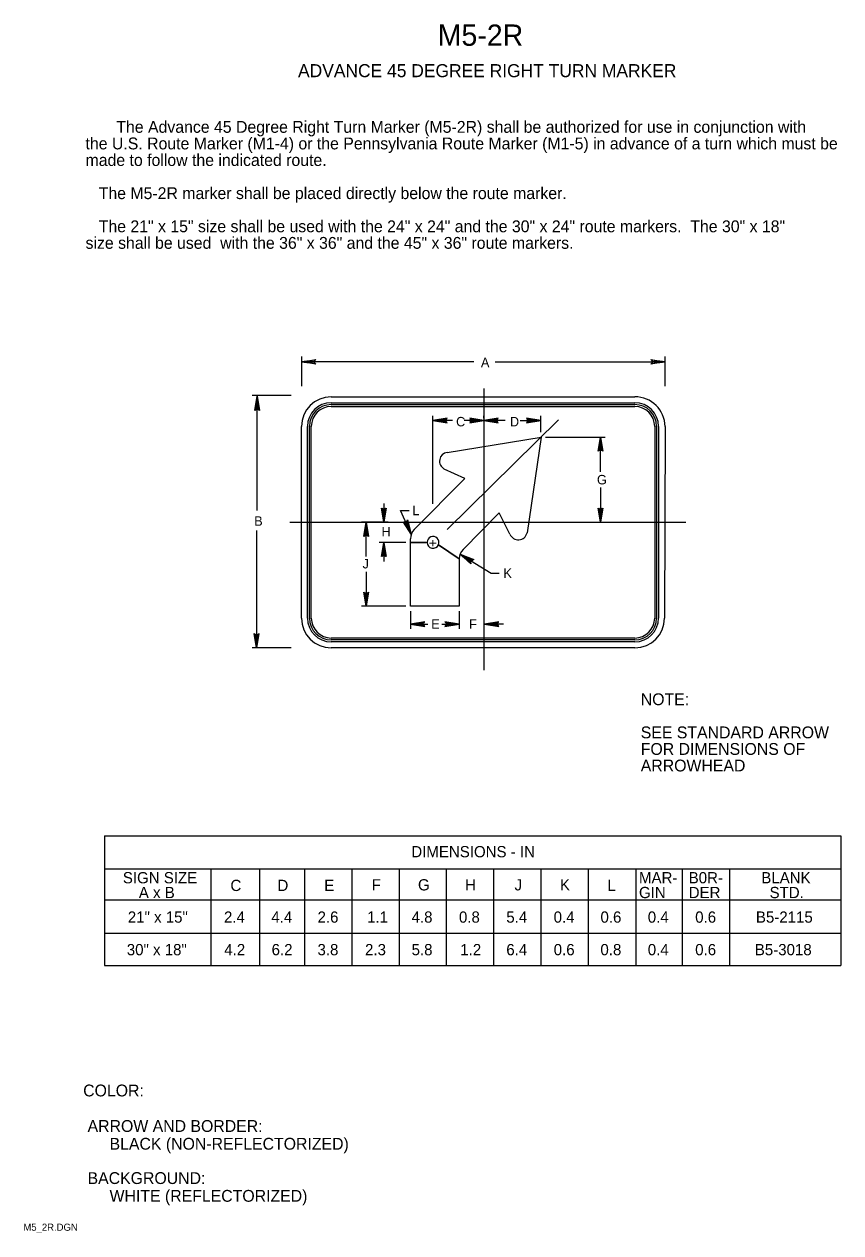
# Model space of a CAD drawing. Extents: x 0.013 to 0.185, y 0.004 to 0.259.
import ezdxf

# ---------------------------------------------------------------- set-up
doc = ezdxf.new("R2010")
doc.units = 0
for name, color, linetype in [('1', 7, 'Continuous'), ('2', 7, 'Continuous'), ('3', 7, 'Continuous')]:
    doc.layers.add(name, color=color, linetype=linetype)

msp = doc.modelspace()

# ---------------------------------------------------------------- linework, layer by layer
at = {"layer": '1'}
for p, q in [((0.185125, 0.08775000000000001), (0.185125, 0.060375)), ((0.16160297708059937, 0.08080009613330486), (0.16160297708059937, 0.06042509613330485))]:
    msp.add_line(p, q, dxfattribs=at)
at = {"layer": '2'}
for p, q in [((0.029625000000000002, 0.08775000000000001), (0.185125, 0.08775000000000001)), ((0.029625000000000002, 0.08775000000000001), (0.029625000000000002, 0.060375)), ((0.185125, 0.08075), (0.029625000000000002, 0.08075)), ((0.05210297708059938, 0.08080009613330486), (0.05210297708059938, 0.06042509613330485)), ((0.062375, 0.08075), (0.062375, 0.060375)), ((0.07187500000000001, 0.08075), (0.07187500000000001, 0.060375)), ((0.081875, 0.08075), (0.081875, 0.060375)), ((0.091875, 0.08075), (0.091875, 0.060375)), ((0.10175000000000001, 0.08075), (0.10175000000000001, 0.060375)), ((0.11175, 0.08075), (0.11175, 0.060375)), ((0.12175, 0.08075), (0.12175, 0.060375)), ((0.13175, 0.08075), (0.13175, 0.060375)), ((0.14185297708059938, 0.08080009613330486), (0.14185297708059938, 0.06042509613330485)), ((0.1516029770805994, 0.08080009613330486), (0.1516029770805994, 0.06042509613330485)), ((0.029625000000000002, 0.07425), (0.185125, 0.07425)), ((0.029625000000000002, 0.06725), (0.185125, 0.06725)), ((0.029625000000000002, 0.060375), (0.185125, 0.060375))]:
    msp.add_line(p, q, dxfattribs=at)
at = {"layer": '3'}
for p, q in [((0.07127993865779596, 0.1827356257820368), (0.07127993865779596, 0.18898593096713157)), ((0.148007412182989, 0.1827356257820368), (0.148007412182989, 0.18898593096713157)), ((0.07125000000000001, 0.18787500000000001), (0.07425, 0.18837500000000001)), ((0.074125, 0.18825), (0.07125000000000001, 0.18787500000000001)), ((0.07125000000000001, 0.18787500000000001), (0.074, 0.188)), ((0.074, 0.18775), (0.07125000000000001, 0.18787500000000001)), ((0.07125000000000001, 0.18787500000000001), (0.074125, 0.1875)), ((0.07425, 0.187375), (0.07125000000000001, 0.18787500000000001)), ((0.10761351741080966, 0.1878690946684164), (0.07126137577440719, 0.18786379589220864)), ((0.074, 0.188), (0.074125, 0.18825)), ((0.074125, 0.1875), (0.074, 0.18775)), ((0.07425, 0.18837500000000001), (0.074125, 0.18825)), ((0.074125, 0.1875), (0.07425, 0.187375)), ((0.11211351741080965, 0.1878690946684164), (0.14798851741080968, 0.18786379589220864)), ((0.145125, 0.18825), (0.145, 0.18837500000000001)), ((0.145, 0.18837500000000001), (0.148, 0.18787500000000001)), ((0.148, 0.18787500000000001), (0.145, 0.187375)), ((0.145, 0.187375), (0.145125, 0.1875)), ((0.145125, 0.18825), (0.14525, 0.188)), ((0.148, 0.18787500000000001), (0.145125, 0.18825)), ((0.145125, 0.1875), (0.148, 0.18787500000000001)), ((0.14525, 0.18775), (0.145125, 0.1875)), ((0.14525, 0.188), (0.148, 0.18787500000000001)), ((0.148, 0.18787500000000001), (0.14525, 0.18775)), ((0.10975, 0.18225), (0.10975, 0.12275)), ((0.06905786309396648, 0.18078209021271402), (0.060780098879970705, 0.18078209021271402)), ((0.061375, 0.177625), (0.061875, 0.180625)), ((0.061875, 0.180625), (0.0615, 0.17775)), ((0.06175, 0.177875), (0.061875, 0.180625)), ((0.06186351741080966, 0.15649756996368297), (0.06186351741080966, 0.18077012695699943)), ((0.061875, 0.180625), (0.062, 0.177875)), ((0.06225, 0.17775), (0.061875, 0.180625)), ((0.061875, 0.180625), (0.062375, 0.177625)), ((0.0775, 0.1805), (0.141625, 0.1805)), ((0.0775, 0.17925), (0.141625, 0.17925)), ((0.0775, 0.17885), (0.141625, 0.17885)), ((0.0615, 0.17775), (0.061375, 0.177625)), ((0.0615, 0.17775), (0.06175, 0.177875)), ((0.062, 0.177875), (0.06225, 0.17775)), ((0.062375, 0.177625), (0.06225, 0.17775)), ((0.0775, 0.17845), (0.141625, 0.17845)), ((0.099, 0.15787500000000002), (0.099, 0.1765)), ((0.10975, 0.176), (0.10975, 0.1765)), ((0.12175, 0.17300000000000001), (0.12175, 0.1765)), ((0.07125000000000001, 0.13375), (0.07125000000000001, 0.17425000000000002)), ((0.0725, 0.13375), (0.0725, 0.17425000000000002)), ((0.0729, 0.13375), (0.0729, 0.17425000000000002)), ((0.07330000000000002, 0.13375), (0.07330000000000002, 0.17425000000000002)), ((0.10200000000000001, 0.176), (0.099, 0.17550000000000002)), ((0.099, 0.17550000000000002), (0.10187500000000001, 0.175875)), ((0.10175000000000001, 0.175625), (0.099, 0.17550000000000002)), ((0.10312500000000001, 0.17550000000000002), (0.099, 0.17550000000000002)), ((0.099, 0.17550000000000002), (0.10175000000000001, 0.175375)), ((0.10187500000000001, 0.175125), (0.099, 0.17550000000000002)), ((0.099, 0.17550000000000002), (0.10200000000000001, 0.17500000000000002)), ((0.10187500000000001, 0.175875), (0.10175000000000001, 0.175625)), ((0.10175000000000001, 0.175375), (0.10187500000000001, 0.175125)), ((0.10187500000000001, 0.175875), (0.10200000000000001, 0.176)), ((0.10200000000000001, 0.17500000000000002), (0.10187500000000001, 0.175125)), ((0.1255, 0.175625), (0.10200000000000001, 0.1525)), ((0.10973851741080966, 0.1754947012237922), (0.10561351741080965, 0.1754947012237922)), ((0.10975, 0.17550000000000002), (0.10675, 0.176)), ((0.10675, 0.176), (0.106875, 0.175875)), ((0.10675, 0.17500000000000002), (0.10975, 0.17550000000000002)), ((0.106875, 0.175125), (0.10675, 0.17500000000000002)), ((0.107, 0.175625), (0.106875, 0.175875)), ((0.106875, 0.175875), (0.10975, 0.17550000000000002)), ((0.10975, 0.17550000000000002), (0.106875, 0.175125)), ((0.106875, 0.175125), (0.107, 0.175375)), ((0.10975, 0.17550000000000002), (0.107, 0.175625)), ((0.107, 0.175375), (0.10975, 0.17550000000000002)), ((0.11275, 0.176), (0.10975, 0.17550000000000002)), ((0.10975, 0.17550000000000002), (0.112625, 0.175875)), ((0.1125, 0.175625), (0.10975, 0.17550000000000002)), ((0.11375, 0.17550000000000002), (0.10975, 0.17550000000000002)), ((0.10975, 0.17550000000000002), (0.1125, 0.175375)), ((0.112625, 0.175125), (0.10975, 0.17550000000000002)), ((0.10975, 0.17550000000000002), (0.11275, 0.17500000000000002)), ((0.11423851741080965, 0.1754947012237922), (0.11023851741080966, 0.1754947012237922)), ((0.112625, 0.175875), (0.1125, 0.175625)), ((0.1125, 0.175375), (0.112625, 0.175125)), ((0.112625, 0.175875), (0.11275, 0.176)), ((0.11275, 0.17500000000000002), (0.112625, 0.175125)), ((0.11737500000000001, 0.17550000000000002), (0.12175, 0.17550000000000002)), ((0.12175, 0.17550000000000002), (0.11875000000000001, 0.176)), ((0.11875000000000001, 0.176), (0.11887500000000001, 0.175875)), ((0.11875000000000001, 0.17500000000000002), (0.12175, 0.17550000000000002)), ((0.11887500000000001, 0.175125), (0.11875000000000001, 0.17500000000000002)), ((0.11900000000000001, 0.175625), (0.11887500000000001, 0.175875)), ((0.11887500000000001, 0.175875), (0.12175, 0.17550000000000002)), ((0.12175, 0.17550000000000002), (0.11887500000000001, 0.175125)), ((0.11887500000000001, 0.175125), (0.11900000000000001, 0.175375)), ((0.12175, 0.17550000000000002), (0.11900000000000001, 0.175625)), ((0.11900000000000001, 0.175375), (0.12175, 0.17550000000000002)), ((0.14582499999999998, 0.17425000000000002), (0.14582499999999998, 0.13375)), ((0.146225, 0.17425000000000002), (0.146225, 0.13375)), ((0.146625, 0.17425000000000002), (0.146625, 0.13375)), ((0.148, 0.17425000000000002), (0.147875, 0.13375)), ((0.10200000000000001, 0.16875), (0.121875, 0.17200000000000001)), ((0.121875, 0.17200000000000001), (0.11887500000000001, 0.15175)), ((0.12275, 0.17200000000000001), (0.135375, 0.17200000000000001)), ((0.133875, 0.169), (0.134375, 0.17200000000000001)), ((0.134375, 0.17200000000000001), (0.134, 0.169125)), ((0.13425, 0.16925), (0.134375, 0.17200000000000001)), ((0.134375, 0.164625), (0.134375, 0.17200000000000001)), ((0.134375, 0.17200000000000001), (0.1345, 0.16925)), ((0.13475, 0.169125), (0.134375, 0.17200000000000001)), ((0.134375, 0.17200000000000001), (0.134875, 0.169)), ((0.134, 0.169125), (0.133875, 0.169)), ((0.134, 0.169125), (0.13425, 0.16925)), ((0.1345, 0.16925), (0.13475, 0.169125)), ((0.134875, 0.169), (0.13475, 0.169125)), ((0.10575, 0.16325), (0.101375, 0.16525)), ((0.095, 0.1525), (0.10575, 0.16325)), ((0.134375, 0.161375), (0.134375, 0.154)), ((0.088625, 0.154), (0.088125, 0.157)), ((0.088125, 0.157), (0.08825, 0.15687500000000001)), ((0.0885, 0.15675), (0.08825, 0.15687500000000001)), ((0.08825, 0.15687500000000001), (0.088625, 0.154)), ((0.088625, 0.154), (0.0885, 0.15675)), ((0.088625, 0.158), (0.088625, 0.154)), ((0.089125, 0.157), (0.088625, 0.154)), ((0.088625, 0.154), (0.089, 0.15687500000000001)), ((0.08875, 0.15675), (0.088625, 0.154)), ((0.089, 0.15687500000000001), (0.08875, 0.15675)), ((0.089, 0.15687500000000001), (0.089125, 0.157)), ((0.092125, 0.1565), (0.094, 0.1565)), ((0.094375, 0.1515), (0.092125, 0.1565)), ((0.113, 0.156), (0.105375, 0.14825)), ((0.11525, 0.1515), (0.113, 0.156)), ((0.134375, 0.154), (0.133875, 0.157)), ((0.133875, 0.157), (0.134, 0.15687500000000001)), ((0.13425, 0.15675), (0.134, 0.15687500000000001)), ((0.134, 0.15687500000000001), (0.134375, 0.154)), ((0.134375, 0.154), (0.13425, 0.15675)), ((0.134875, 0.157), (0.134375, 0.154)), ((0.134375, 0.154), (0.13475, 0.15687500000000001)), ((0.1345, 0.15675), (0.134375, 0.154)), ((0.13475, 0.15687500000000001), (0.1345, 0.15675)), ((0.13475, 0.15687500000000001), (0.134875, 0.157)), ((0.06875, 0.154), (0.152375, 0.154)), ((0.088875, 0.154), (0.083875, 0.154)), ((0.084375, 0.151), (0.084875, 0.154)), ((0.084875, 0.154), (0.0845, 0.151125)), ((0.08475, 0.15125), (0.084875, 0.154)), ((0.084875, 0.14675), (0.084875, 0.154)), ((0.084875, 0.154), (0.085, 0.15125)), ((0.08525, 0.151125), (0.084875, 0.154)), ((0.084875, 0.154), (0.085375, 0.151)), ((0.0895, 0.154), (0.08762500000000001, 0.154)), ((0.094375, 0.1515), (0.09275, 0.154)), ((0.09275, 0.154), (0.092875, 0.154)), ((0.093125, 0.154), (0.092875, 0.154)), ((0.092875, 0.154), (0.094375, 0.1515)), ((0.094375, 0.1515), (0.093125, 0.154)), ((0.0935, 0.15425), (0.093375, 0.154125)), ((0.093375, 0.154125), (0.094375, 0.1515)), ((0.0935, 0.15425), (0.093625, 0.1545)), ((0.094375, 0.1515), (0.0935, 0.15425)), ((0.093625, 0.1545), (0.094375, 0.1515)), ((0.133625, 0.154), (0.135375, 0.154)), ((0.06175, 0.15225421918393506), (0.06175, 0.1275)), ((0.0845, 0.151125), (0.084375, 0.151)), ((0.0845, 0.151125), (0.08475, 0.15125)), ((0.085, 0.15125), (0.08525, 0.151125)), ((0.085375, 0.151), (0.08525, 0.151125)), ((0.0932302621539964, 0.14975), (0.08762500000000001, 0.14975)), ((0.088125, 0.14675), (0.088625, 0.14975)), ((0.088625, 0.14975), (0.08825, 0.146875)), ((0.0885, 0.147), (0.088625, 0.14975)), ((0.088625, 0.14775), (0.088625, 0.14975)), ((0.088625, 0.14975), (0.08875, 0.147)), ((0.089, 0.146875), (0.088625, 0.14975)), ((0.088625, 0.14975), (0.089125, 0.14675)), ((0.09425, 0.14975), (0.09425, 0.1505)), ((0.09775, 0.14975), (0.09425, 0.14975)), ((0.09425, 0.14975), (0.09775, 0.14975)), ((0.09425, 0.13625), (0.09425, 0.14975)), ((0.1045, 0.14625), (0.1001544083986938, 0.14927058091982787)), ((0.1001544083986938, 0.14927058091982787), (0.1045, 0.14625)), ((0.08825, 0.146875), (0.088125, 0.14675)), ((0.08825, 0.146875), (0.0885, 0.147)), ((0.088625, 0.14775), (0.088625, 0.14575)), ((0.08875, 0.147), (0.089, 0.146875)), ((0.089125, 0.14675), (0.089, 0.146875)), ((0.1045, 0.14625), (0.1045, 0.13625)), ((0.10475, 0.14725), (0.11125, 0.14325000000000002)), ((0.107, 0.145625), (0.10475, 0.14725)), ((0.10475, 0.14725), (0.107, 0.145375)), ((0.107, 0.14525), (0.10475, 0.14725)), ((0.10475, 0.14725), (0.107125, 0.145875)), ((0.107375, 0.146), (0.10475, 0.14725)), ((0.10475, 0.14725), (0.107625, 0.146125)), ((0.107, 0.145375), (0.107, 0.145625)), ((0.107125, 0.145875), (0.107375, 0.146)), ((0.107625, 0.146125), (0.107375, 0.146)), ((0.084875, 0.14350000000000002), (0.084875, 0.13625)), ((0.107, 0.145375), (0.107, 0.14525)), ((0.11125, 0.14325000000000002), (0.113, 0.14325000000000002)), ((0.084875, 0.13625), (0.084375, 0.13925)), ((0.084375, 0.13925), (0.0845, 0.139125)), ((0.08475, 0.139), (0.0845, 0.139125)), ((0.0845, 0.139125), (0.084875, 0.13625)), ((0.084875, 0.13625), (0.08475, 0.139)), ((0.085375, 0.13925), (0.084875, 0.13625)), ((0.084875, 0.13625), (0.08525, 0.139125)), ((0.085, 0.139), (0.084875, 0.13625)), ((0.08525, 0.139125), (0.085, 0.139)), ((0.08525, 0.139125), (0.085375, 0.13925)), ((0.09325, 0.13625), (0.083875, 0.13625)), ((0.1045, 0.13625), (0.09425, 0.13625)), ((0.09425, 0.13525), (0.09425, 0.1315)), ((0.09725, 0.133), (0.09425, 0.1325)), ((0.09425, 0.1325), (0.097125, 0.132875)), ((0.097125, 0.132875), (0.097, 0.132625)), ((0.097125, 0.132875), (0.09725, 0.133)), ((0.1045, 0.1325), (0.1015, 0.133)), ((0.1015, 0.133), (0.10162500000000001, 0.132875)), ((0.10175000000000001, 0.132625), (0.10162500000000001, 0.132875)), ((0.10162500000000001, 0.132875), (0.1045, 0.1325)), ((0.1045, 0.13525), (0.1045, 0.1315)), ((0.112875, 0.133), (0.109875, 0.1325)), ((0.109875, 0.1325), (0.11275, 0.132875)), ((0.11275, 0.132875), (0.112625, 0.132625)), ((0.11275, 0.132875), (0.112875, 0.133)), ((0.06175, 0.1275), (0.06125, 0.1305)), ((0.06125, 0.1305), (0.061375, 0.130375)), ((0.061625, 0.13025), (0.061375, 0.130375)), ((0.061375, 0.130375), (0.06175, 0.1275)), ((0.06175, 0.1275), (0.061625, 0.13025)), ((0.06225, 0.1305), (0.06175, 0.1275)), ((0.06175, 0.1275), (0.062125, 0.130375)), ((0.061875, 0.13025), (0.06175, 0.1275)), ((0.062125, 0.130375), (0.061875, 0.13025)), ((0.062125, 0.130375), (0.06225, 0.1305)), ((0.097, 0.132625), (0.09425, 0.1325)), ((0.09425, 0.1325), (0.097875, 0.1325)), ((0.09425, 0.1325), (0.097, 0.132375)), ((0.097125, 0.132125), (0.09425, 0.1325)), ((0.09425, 0.1325), (0.09725, 0.132)), ((0.097, 0.132375), (0.097125, 0.132125)), ((0.09725, 0.132), (0.097125, 0.132125)), ((0.100875, 0.1325), (0.1045, 0.1325)), ((0.1015, 0.132), (0.1045, 0.1325)), ((0.10162500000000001, 0.132125), (0.1015, 0.132)), ((0.1045, 0.1325), (0.10162500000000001, 0.132125)), ((0.10162500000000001, 0.132125), (0.10175000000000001, 0.132375)), ((0.1045, 0.1325), (0.10175000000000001, 0.132625)), ((0.10175000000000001, 0.132375), (0.1045, 0.1325)), ((0.112625, 0.132625), (0.109875, 0.1325)), ((0.113875, 0.1325), (0.109875, 0.1325)), ((0.109875, 0.1325), (0.112625, 0.132375)), ((0.11275, 0.132125), (0.109875, 0.1325)), ((0.109875, 0.1325), (0.112875, 0.132)), ((0.112625, 0.132375), (0.11275, 0.132125)), ((0.112875, 0.132), (0.11275, 0.132125)), ((0.141625, 0.12955000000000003), (0.0775, 0.12955000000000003)), ((0.141625, 0.12915000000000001), (0.0775, 0.12915000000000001)), ((0.141625, 0.12875), (0.0775, 0.12875)), ((0.06905786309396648, 0.1274933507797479), (0.06082493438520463, 0.1274933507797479)), ((0.141625, 0.1275), (0.0775, 0.1275))]:
    msp.add_line(p, q, dxfattribs=at)
for centre, radius, start, end in [((0.07749999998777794, 0.17425000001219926), 0.0062499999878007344, 90, 180), ((0.07749999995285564, 0.1742500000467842), 0.004999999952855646, 90, 180), ((0.07749999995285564, 0.1742500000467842), 0.0045999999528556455, 90, 180), ((0.1416874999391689, 0.17418749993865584), 0.0063128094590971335, 0.5672666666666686, 90.56726666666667), ((0.14162499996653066, 0.17424999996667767), 0.0050000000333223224, 0, 90), ((0.14162499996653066, 0.17424999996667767), 0.004600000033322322, 0, 90), ((0.07749999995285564, 0.1742500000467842), 0.004199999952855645, 90, 180), ((0.14162499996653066, 0.17424999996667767), 0.004200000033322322, 0, 90), ((0.10225614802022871, 0.16689845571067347), 0.0018691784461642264, 97.87646944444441, 241.8741861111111), ((0.09724249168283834, 0.15052612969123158), 0.002992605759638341, 138.86674166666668, 180.50028055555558), ((0.099, 0.14975), 0.00125, 337.44717856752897, 180), ((0.11702188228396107, 0.15221395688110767), 0.0019103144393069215, 201.94632777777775, 345.94404444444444), ((0.099, 0.14975), 0.00125, 180, 337.447178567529), ((0.10735171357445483, 0.1461937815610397), 0.0028522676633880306, 133.87062222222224, 178.87062222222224), ((0.07750000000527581, 0.13375000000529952), 0.006250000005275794, 180, 270), ((0.07749999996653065, 0.13374999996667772), 0.004999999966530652, 180, 270), ((0.07749999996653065, 0.13374999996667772), 0.004599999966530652, 180, 270), ((0.07749999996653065, 0.13374999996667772), 0.004199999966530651, 180, 270), ((0.14162500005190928, 0.13374999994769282), 0.004999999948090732, 270, 0), ((0.14162500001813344, 0.13374999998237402), 0.006249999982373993, 270, 0), ((0.14162500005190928, 0.13374999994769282), 0.004599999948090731, 270, 0), ((0.14162500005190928, 0.13374999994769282), 0.004199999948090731, 270, 0)]:
    msp.add_arc(centre, radius, start, end, dxfattribs=at)

# ---------------------------------------------------------------- texts
at = {"layer": '1'}
for s, height, p in [('M5-2R', 0.0045000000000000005, (0.1, 0.254625)), ('ADVANCE 45 DEGREE RIGHT TURN MARKER', 0.00275025, (0.07050000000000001, 0.248)), ('MAR-', 0.0023752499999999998, (0.14250000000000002, 0.07775)), ('B0R-', 0.0023752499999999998, (0.153, 0.07775)), ('BLANK', 0.0023752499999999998, (0.1683277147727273, 0.07775)), ('GIN', 0.0023752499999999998, (0.14250000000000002, 0.074625)), ('DER', 0.0023752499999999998, (0.153, 0.074625)), ('STD.', 0.0023752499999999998, (0.1700777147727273, 0.074625)), ('COLOR:', 0.0024997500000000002, (0.025125, 0.03275)), (' ARROW AND BORDER:', 0.0024997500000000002, (0.025125, 0.02525)), ('      BLACK (NON-REFLECTORIZED)', 0.0024997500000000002, (0.025125, 0.021500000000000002)), (' BACKGROUND:', 0.0024997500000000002, (0.025125, 0.01425)), ('      WHITE (REFLECTORIZED)', 0.0024997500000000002, (0.025125, 0.0105)), ('M5_2R.DGN', 0.0015, (0.0125, 0.004375))]:
    msp.add_text(s, height=height, dxfattribs=at).set_placement(p)
at = {"layer": '2'}
for s, height, p in [('       The Advance 45 Degree Right Turn Marker (M5-2R) shall be authorized for use in conjunction with ', 0.0024997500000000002, (0.025625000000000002, 0.23625025)), ('the U.S. Route Marker (M1-4) or the Pennsylvania Route Marker (M1-5) in advance of a turn which must be ', 0.0024997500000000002, (0.025625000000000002, 0.2327505)), ('made to follow the indicated route.', 0.0024997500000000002, (0.025625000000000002, 0.22925075)), ('   The M5-2R marker shall be placed directly below the route marker.', 0.0024997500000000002, (0.025625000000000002, 0.22225125)), ('   The 21" x 15" size shall be used with the 24" x 24" and the 30" x 24" route markers.  The 30" x 18" ', 0.0024997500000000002, (0.025625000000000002, 0.21525175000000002)), ('size shall be used  with the 36" x 36" and the 45" x 36" route markers.', 0.0024997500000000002, (0.025625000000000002, 0.21175200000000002)), ('DIMENSIONS - IN', 0.0023752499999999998, (0.09441729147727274, 0.08325)), ('SIGN SIZE', 0.0023752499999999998, (0.0335, 0.07775)), ('A x B', 0.0023752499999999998, (0.036875, 0.074625)), ('C', 0.0023752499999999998, (0.05622528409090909, 0.076125)), ('D', 0.0023752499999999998, (0.06615726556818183, 0.076125)), ('E', 0.0023752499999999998, (0.07603430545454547, 0.076125)), ('F', 0.0023752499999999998, (0.08606489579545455, 0.07625)), ('G', 0.0023752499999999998, (0.0958304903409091, 0.07625)), ('H', 0.0023752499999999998, (0.1057891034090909, 0.07625)), ('J', 0.0023752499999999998, (0.1162144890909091, 0.07625)), ('K', 0.0023752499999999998, (0.12580709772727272, 0.07625)), ('L', 0.0023752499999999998, (0.13583684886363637, 0.076125))]:
    msp.add_text(s, height=height, dxfattribs=at).set_placement(p)
at = {"layer": '3'}
for s, height, p in [('A', 0.00200025, (0.109125, 0.18675)), ('C', 0.00200025, (0.10387500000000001, 0.17425000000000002)), ('D', 0.00200025, (0.11525, 0.17425000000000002)), ('G', 0.00200025, (0.133625, 0.162)), ('L', 0.00200025, (0.094625, 0.1555)), ('B', 0.00200025, (0.06125, 0.15325)), ('H', 0.00200025, (0.088125, 0.151)), ('J', 0.00200025, (0.084125, 0.14425)), ('K', 0.00200025, (0.113875, 0.14225000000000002)), ('E', 0.00200025, (0.098625, 0.1315)), ('F', 0.00200025, (0.106625, 0.1315)), ('NOTE:', 0.0024997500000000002, (0.142875, 0.115375)), ('SEE STANDARD ARROW', 0.0024997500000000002, (0.142875, 0.108375)), ('FOR DIMENSIONS OF', 0.0024997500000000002, (0.142875, 0.104875)), ('ARROWHEAD', 0.0024997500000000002, (0.142875, 0.101375)), ('21" x 15"', 0.0023752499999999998, (0.03455227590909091, 0.06943737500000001)), ('2.4', 0.0023752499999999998, (0.054856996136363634, 0.06943737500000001)), ('4.4', 0.0023752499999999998, (0.06485699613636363, 0.06943737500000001)), ('2.6', 0.0023752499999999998, (0.0746185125, 0.06943737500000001)), ('1.1', 0.0023752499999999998, (0.08508132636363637, 0.06943737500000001)), ('4.8', 0.0023752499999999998, (0.09448055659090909, 0.06943737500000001)), ('0.8', 0.0023752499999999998, (0.10448055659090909, 0.06943737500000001)), ('5.4', 0.0023752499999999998, (0.11448199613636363, 0.06943737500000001)), ('0.4', 0.0023752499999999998, (0.12448199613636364, 0.06943737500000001)), ('0.6', 0.0023752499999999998, (0.1343685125, 0.06943737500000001)), ('0.4', 0.0023752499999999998, (0.14435699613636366, 0.06943737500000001)), ('0.6', 0.0023752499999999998, (0.1543685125, 0.06943737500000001)), ('B5-2115', 0.0023752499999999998, (0.1671897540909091, 0.06943737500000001)), ('30" x 18"', 0.0023752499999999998, (0.0343363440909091, 0.062562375)), ('4.2', 0.0023752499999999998, (0.05491997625, 0.062562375)), ('6.2', 0.0023752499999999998, (0.06491997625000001, 0.062562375)), ('3.8', 0.0023752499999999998, (0.07460555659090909, 0.062562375)), ('2.3', 0.0023752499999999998, (0.08465306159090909, 0.062562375)), ('5.8', 0.0023752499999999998, (0.09448055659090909, 0.062562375)), ('1.2', 0.0023752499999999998, (0.10476090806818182, 0.062562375)), ('6.4', 0.0023752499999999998, (0.11448199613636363, 0.062562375)), ('0.6', 0.0023752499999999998, (0.1244935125, 0.062562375)), ('0.8', 0.0023752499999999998, (0.1343555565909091, 0.062562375)), ('0.4', 0.0023752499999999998, (0.14435699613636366, 0.062562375)), ('0.6', 0.0023752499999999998, (0.1543685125, 0.062562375)), ('B5-3018', 0.0023752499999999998, (0.1669579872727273, 0.062562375))]:
    msp.add_text(s, height=height, dxfattribs=at).set_placement(p)
msp.add_text('+', height=0.00200025, rotation=270, dxfattribs=at).set_placement((0.098, 0.150375))

doc.saveas('drawing.dxf')
